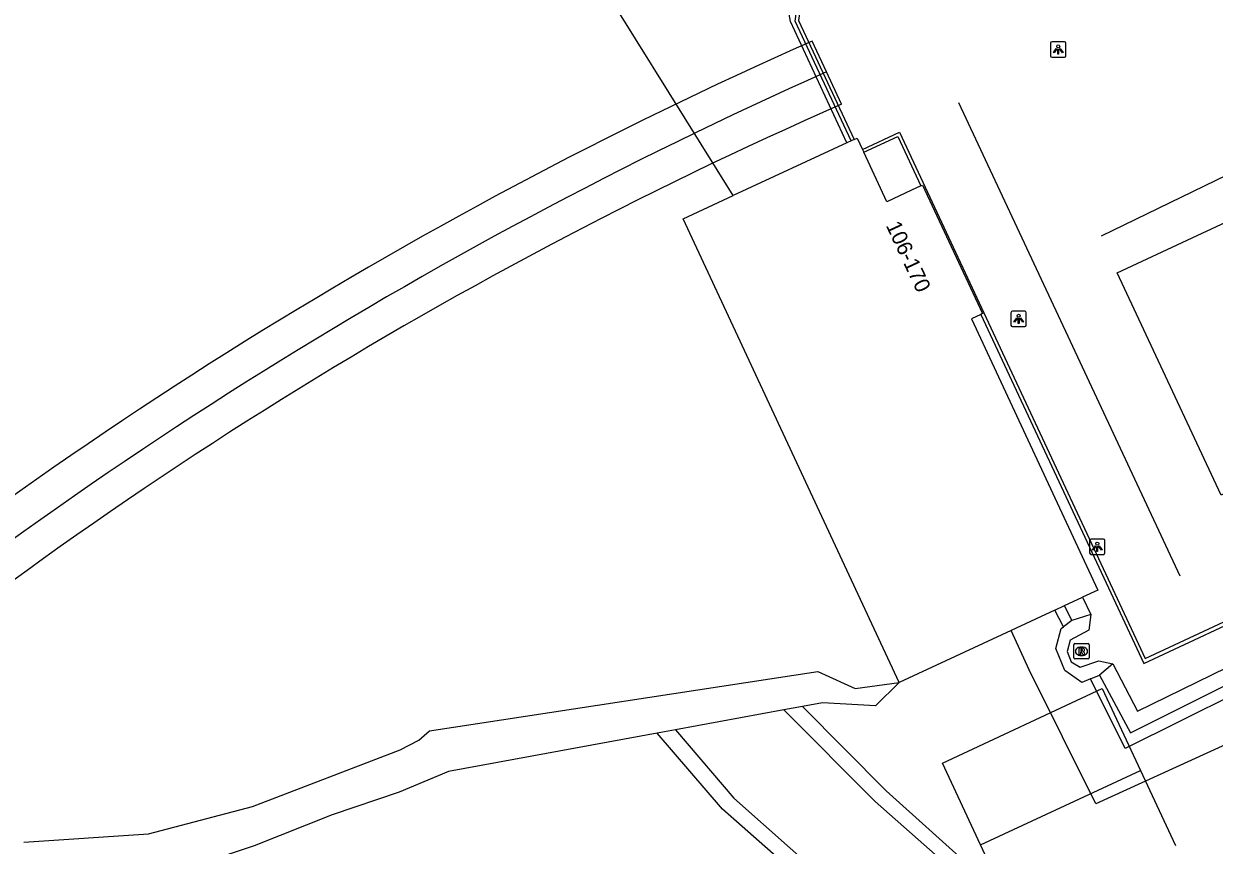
# Model space of a CAD drawing. Extents: x 155640 to 156810, y 382822 to 384046.
# Drawn here: x 156352.8 to 156430.2, y 383607 to 383660.4 of the extents above; entities that cross this region are included whole.
import ezdxf

# ---------------------------------------------------------------- set-up
doc = ezdxf.new("R2010")
doc.units = 0
for name, color, linetype in [('IMGEO_Dek', 7, 'Continuous'), ('IMGEO_Fietspad_gesloten', 7, 'Continuous'), ('IMGEO_Groenvoorziening', 7, 'Continuous'), ('IMGEO_Lichtpunt', 7, 'Continuous'), ('IMGEO_Lijnafwatering', 7, 'Continuous'), ('IMGEO_Meer_plas_ven_vijver', 7, 'Continuous'), ('IMGEO_Muur', 7, 'Continuous'), ('IMGEO_Pand', 7, 'Continuous'), ('IMGEO_Pand_nummerreeks', 7, 'Continuous'), ('IMGEO_Pand_vergunning_verleend', 7, 'Continuous'), ('IMGEO_Rioolput', 7, 'Continuous'), ('IMGEO_Voetgangersgebied_gesloten', 7, 'Continuous'), ('IMGEO_Voetpad_open', 7, 'Continuous')]:
    doc.layers.add(name, color=color, linetype=linetype)

msp = doc.modelspace()

# ---------------------------------------------------------------- linework, layer by layer
at = {"layer": 'IMGEO_Dek'}
msp.add_lwpolyline([(156405.984, 383655.206), (156404.997, 383657.316), (156404.061, 383659.318)], dxfattribs=at)
for centre, radius, start, end in [((156524.71, 383386.919), 297.922, 113.88918, 130.50491), ((156520.895, 383392.973), 286.305, 113.66314, 130.7058)]:
    msp.add_arc(centre, radius, start, end, dxfattribs=at)
at = {"layer": 'IMGEO_Fietspad_gesloten'}
msp.add_lwpolyline([(156404.997, 383657.316), (156404.061, 383659.318)], dxfattribs=at)
for centre, radius, start, end in [((156524.71, 383386.919), 297.922, 113.88918, 130.50491), ((156526.23, 383385.16), 297.937, 114.01083, 130.50472)]:
    msp.add_arc(centre, radius, start, end, dxfattribs=at)
at = {"layer": 'IMGEO_Groenvoorziening'}
for points in [[(156423.637, 383618.795), (156425.236, 383615.708), (156449.521, 383627.575), (156458.696, 383607.173), (156460.114, 383604.619), (156489.605, 383581.396), (156489.812, 383580.164), (156489.269, 383579.114), (156487.523, 383577.898), (156486.752, 383578.045), (156485.235, 383578.757), (156457.287, 383600.998), (156455.379, 383602.928), (156453.641, 383605.853), (156447.188, 383620.939), (156422.522, 383609.671), (156418.19, 383618.402), (156417.016, 383620.957)], [(156422.776, 383618.049), (156424.785, 383614.287), (156449.137, 383626.484), (156456.722, 383608.221), (156458.385, 383605.29), (156459.691, 383603.715), (156488.187, 383581.203), (156487.643, 383580.547), (156459.772, 383602.626), (156457.864, 383604.504), (156456.117, 383607.727), (156449.565, 383623.152), (156448.725, 383624.069), (156447.36, 383624.401), (156446.083, 383624.028), (156424.433, 383613.283), (156422.191, 383617.807)], [(156421.652, 383623.116), (156422.197, 383621.989)], [(156420.973, 383621.613), (156420.487, 383622.573)], [(156420.426, 383621.202), (156419.863, 383622.283)], [(156420.973, 383621.613), (156420.426, 383621.202)], [(156422.197, 383621.989), (156422.08, 383620.972), (156420.869, 383620.328), (156420.673, 383619.584), (156420.925, 383618.907), (156421.504, 383618.559), (156422.734, 383618.972), (156423.637, 383618.795)], [(156422.197, 383621.989), (156420.973, 383621.613)], [(156422.191, 383617.807), (156421.617, 383617.569), (156420.502, 383618.345), (156419.933, 383619.784), (156420.283, 383621.094), (156420.426, 383621.202)], [(156423.637, 383618.795), (156422.776, 383618.049)], [(156422.191, 383617.807), (156422.776, 383618.049)], [(156409.738, 383617.568), (156408.186, 383616.056), (156404.738, 383616.259), (156403.435, 383616.019)], [(156402.228, 383615.797), (156395.166, 383614.497)], [(156403.435, 383616.019), (156402.228, 383615.797)], [(156403.435, 383616.019), (156408.885, 383610.517), (156456.925, 383567.29), (156469.743, 383551.737), (156475.686, 383545.302), (156477.499, 383542.266), (156478.635, 383538.351), (156478.41, 383535.519), (156475.332, 383528.135), (156473.875, 383523.767), (156474.636, 383528.369), (156477.059, 383535.306), (156477.459, 383538.408), (156475.537, 383543.744), (156456.156, 383566.696), (156427.539, 383592.711), (156408.16, 383609.82), (156402.228, 383615.797)], [(156393.975, 383614.278), (156380.396, 383611.779), (156377.186, 383610.428), (156372.832, 383608.955), (156367.751, 383606.932), (156362.36, 383605.144), (156360.509, 383604.92), (156355.802, 383604.715), (156350.93, 383604.322), (156345.618, 383604.627), (156343.174, 383604.953), (156342.007, 383605.17), (156339.567, 383605.891), (156335.993, 383608.654), (156334.174, 383610.012)], [(156395.166, 383614.497), (156393.975, 383614.278)], [(156468.184, 383540.764), (156464.582, 383545.494), (156461.269, 383549.707), (156451.177, 383560.656), (156405.557, 383602.864), (156398.24, 383609.323), (156393.975, 383614.278)], [(156395.166, 383614.497), (156398.976, 383610.039), (156406.313, 383603.538), (156451.888, 383561.364), (156461.963, 383550.599), (156465.016, 383546.221), (156468.005, 383541.974)]]:
    msp.add_lwpolyline(points, dxfattribs=at)
at = {"layer": 'IMGEO_Lichtpunt'}
for p, q in [((156419.583, 383659.179), (156419.583, 383658.372)), ((156419.583, 383659.179), (156419.583, 383658.372)), ((156420.485, 383659.274), (156419.677, 383659.274)), ((156420.485, 383659.274), (156419.677, 383659.274)), ((156420.579, 383658.372), (156420.579, 383659.179)), ((156420.579, 383658.372), (156420.579, 383659.179)), ((156419.677, 383658.278), (156420.485, 383658.278)), ((156419.677, 383658.278), (156420.485, 383658.278)), ((156417.91, 383641.739), (156417.102, 383641.739)), ((156417.91, 383641.739), (156417.102, 383641.739)), ((156417.008, 383641.644), (156417.008, 383640.837)), ((156417.008, 383641.644), (156417.008, 383640.837)), ((156418.004, 383640.837), (156418.004, 383641.644)), ((156418.004, 383640.837), (156418.004, 383641.644)), ((156417.102, 383640.743), (156417.91, 383640.743)), ((156417.102, 383640.743), (156417.91, 383640.743)), ((156422.124, 383626.813), (156422.124, 383626.006)), ((156422.124, 383626.813), (156422.124, 383626.006)), ((156423.026, 383626.908), (156422.218, 383626.908)), ((156423.026, 383626.908), (156422.218, 383626.908)), ((156423.12, 383626.006), (156423.12, 383626.813)), ((156423.12, 383626.006), (156423.12, 383626.813)), ((156422.218, 383625.912), (156423.026, 383625.912)), ((156422.218, 383625.912), (156423.026, 383625.912))]:
    msp.add_line(p, q, dxfattribs=at)
for points in [[(156419.957, 383658.843), (156419.996, 383658.815), (156419.808, 383658.553), (156419.77, 383658.58), (156419.957, 383658.843)], [(156420.059, 383658.795), (156420.106, 383658.795), (156420.106, 383658.473), (156420.059, 383658.473), (156420.059, 383658.795)], [(156420.169, 383658.815), (156420.207, 383658.842), (156420.394, 383658.58), (156420.355, 383658.552), (156420.169, 383658.815)], [(156417.382, 383641.308), (156417.421, 383641.28), (156417.233, 383641.018), (156417.195, 383641.045), (156417.382, 383641.308)], [(156417.484, 383641.26), (156417.531, 383641.26), (156417.531, 383640.938), (156417.484, 383640.938), (156417.484, 383641.26)], [(156417.594, 383641.28), (156417.632, 383641.307), (156417.819, 383641.045), (156417.78, 383641.017), (156417.594, 383641.28)], [(156422.498, 383626.477), (156422.537, 383626.449), (156422.349, 383626.187), (156422.311, 383626.214), (156422.498, 383626.477)], [(156422.6, 383626.429), (156422.647, 383626.429), (156422.647, 383626.107), (156422.6, 383626.107), (156422.6, 383626.429)], [(156422.71, 383626.449), (156422.748, 383626.476), (156422.935, 383626.214), (156422.896, 383626.186), (156422.71, 383626.449)]]:
    msp.add_lwpolyline(points, dxfattribs=at)
for centre in [(156420.082, 383658.977), (156417.507, 383641.442), (156422.623, 383626.611)]:
    msp.add_circle(centre, 0.0994, dxfattribs=at)
for centre, start, end in [((156419.677, 383659.179), 90, 180), ((156419.677, 383659.179), 90, 180), ((156420.485, 383659.179), 0, 90), ((156420.485, 383659.179), 0, 90), ((156419.677, 383658.372), 180, 270), ((156419.677, 383658.372), 180, 270), ((156420.485, 383658.372), 270, 0), ((156420.485, 383658.372), 270, 360), ((156417.102, 383641.644), 90, 180), ((156417.102, 383641.644), 90, 180), ((156417.91, 383641.644), 0, 90), ((156417.91, 383641.644), 0, 90), ((156417.102, 383640.837), 180, 270), ((156417.102, 383640.837), 180, 270), ((156417.91, 383640.837), 270, 0), ((156417.91, 383640.837), 270, 360), ((156422.218, 383626.813), 90, 180), ((156422.218, 383626.813), 90, 180), ((156423.026, 383626.813), 0, 90), ((156423.026, 383626.813), 0, 90), ((156422.218, 383626.006), 180, 270), ((156422.218, 383626.006), 180, 270), ((156423.026, 383626.006), 270, 0), ((156423.026, 383626.006), 270, 360)]:
    msp.add_arc(centre, 0.0946, start, end, dxfattribs=at)
at = {"layer": 'IMGEO_Lijnafwatering'}
for points in [[(156413.59, 383655.325), (156420.698, 383640.125)], [(156422.906, 383646.649), (156440.016, 383654.951)], [(156420.698, 383640.125), (156427.998, 383624.514)]]:
    msp.add_lwpolyline(points, dxfattribs=at)
at = {"layer": 'IMGEO_Meer_plas_ven_vijver'}
for points in [[(156398.921, 383649.266), (156388.405, 383666.182)], [(156352.753, 383607.187), (156360.877, 383607.728), (156367.645, 383609.501), (156377.261, 383613.187), (156378.466, 383613.825), (156379.163, 383614.421), (156404.434, 383618.287), (156406.868, 383617.171), (156409.738, 383617.568)]]:
    msp.add_lwpolyline(points, dxfattribs=at)
at = {"layer": 'IMGEO_Muur'}
for points in [[(156409.602, 383685.242), (156407.185, 383679.634), (156406.522, 383675.039), (156405.194, 383675.202), (156403.183, 383660.665), (156406.798, 383652.916)], [(156406.607, 383652.828), (156402.962, 383660.62), (156405.007, 383675.431)], [(156407.34, 383652.267), (156409.758, 383653.398), (156425.737, 383619.126), (156450.602, 383630.716), (156462.175, 383605.969), (156467.181, 383608.237), (156467.858, 383606.862), (156505.409, 383577.593), (156505.213, 383577.392), (156487.476, 383541.686), (156478.262, 383529.882), (156478.847, 383529.078), (156488.235, 383516.182)], [(156407.426, 383652.083), (156409.651, 383653.114), (156411.15, 383649.901)], [(156415.055, 383641.53), (156425.658, 383618.803), (156450.441, 383630.387), (156462.081, 383605.554), (156467.059, 383607.851), (156467.609, 383606.673), (156504.975, 383577.57), (156487.254, 383541.827), (156477.937, 383529.89), (156478.682, 383528.865)]]:
    msp.add_lwpolyline(points, dxfattribs=at)
at = {"layer": 'IMGEO_Pand'}
for points in [[(156454.553, 383640.906), (156430.689, 383629.765), (156423.924, 383644.238), (156458.601, 383660.428)], [(156406.329, 383652.699), (156398.921, 383649.266)], [(156406.607, 383652.828), (156406.329, 383652.699)], [(156406.798, 383652.916), (156406.607, 383652.828)], [(156406.798, 383652.916), (156406.994, 383653.007), (156407.34, 383652.267)], [(156407.34, 383652.267), (156407.426, 383652.083)], [(156411.15, 383649.901), (156410.541, 383649.616), (156408.931, 383648.863), (156407.426, 383652.083)], [(156411.15, 383649.901), (156411.248, 383649.947), (156415.163, 383641.581), (156415.055, 383641.53)], [(156409.738, 383617.568), (156395.678, 383647.763), (156398.921, 383649.266)], [(156415.055, 383641.53), (156414.442, 383641.243), (156422.668, 383623.589), (156421.652, 383623.116)], [(156420.487, 383622.573), (156421.652, 383623.116)], [(156419.863, 383622.283), (156420.487, 383622.573)], [(156419.863, 383622.283), (156417.016, 383620.957)], [(156417.016, 383620.957), (156409.738, 383617.568)]]:
    msp.add_lwpolyline(points, dxfattribs=at)
at = {"layer": 'IMGEO_Pand_vergunning_verleend'}
for points in [[(156415.022, 383606.996), (156412.546, 383612.314), (156422.95, 383617.171), (156425.432, 383611.848)], [(156415.022, 383606.996), (156425.432, 383611.848)], [(156425.432, 383611.848), (156427.709, 383606.967)], [(156417.297, 383602.11), (156415.022, 383606.996)]]:
    msp.add_lwpolyline(points, dxfattribs=at)
at = {"layer": 'IMGEO_Rioolput'}
for p, q in [((156421.096, 383619.176), (156421.096, 383620.028)), ((156421.171, 383620.102), (156422.023, 383620.102)), ((156422.097, 383620.028), (156422.097, 383619.176)), ((156421.607, 383619.322), (156421.582, 383619.322)), ((156421.584, 383619.882), (156421.609, 383619.882)), ((156422.023, 383619.102), (156421.171, 383619.102))]:
    msp.add_line(p, q, dxfattribs=at)
for points in [[(156421.096, 383619.176), (156421.096, 383620.028)], [(156421.171, 383620.102), (156422.023, 383620.102)], [(156422.097, 383620.028), (156422.097, 383619.176)], [(156421.685, 383619.8), (156421.433, 383619.802), (156421.433, 383619.402)], [(156421.433, 383619.402), (156421.557, 383619.402), (156421.557, 383619.564), (156421.568, 383619.564)], [(156421.611, 383619.721), (156421.557, 383619.721), (156421.557, 383619.64)], [(156421.557, 383619.64), (156421.609, 383619.64)], [(156421.615, 383619.535), (156421.686, 383619.402), (156421.826, 383619.402), (156421.761, 383619.528)], [(156422.023, 383619.102), (156421.171, 383619.102)]]:
    msp.add_lwpolyline(points, dxfattribs=at)
for centre, radius, start, end in [((156421.173, 383620.026), 0.0765, 91.55205, 178.44795), ((156421.173, 383620.026), 0.0765, 91.55205, 178.44795), ((156422.021, 383620.026), 0.0765, 1.55205, 88.44795), ((156422.021, 383620.026), 0.0765, 1.55205, 88.44795), ((156421.567, 383619.511), 0.0533, 26.02933, 88.69889), ((156421.593, 383619.829), 0.19, 274.7715, 282.96867), ((156421.617, 383619.625), 0.0964, 77.00612, 93.18647), ((156421.631, 383619.682), 0.0378, 276.66336, 79.67722), ((156421.684, 383619.69), 0.109, 350.36119, 89.41601), ((156421.682, 383619.69), 0.112, 277.58423, 350.98172), ((156421.666, 383619.475), 0.108, 29.51342, 73.79051), ((156421.173, 383619.178), 0.0765, 181.55205, 268.44795), ((156421.173, 383619.178), 0.0765, 181.55205, 268.44795), ((156422.021, 383619.178), 0.0765, 271.55205, 358.44795), ((156422.021, 383619.178), 0.0765, 271.55205, 358.44795)]:
    msp.add_arc(centre, radius, start, end, dxfattribs=at)
for centre, major_axis, ratio, start_param, end_param in [((156421.583, 383619.602), (-0.387, 0.002), 0.722429, 4.712389, 7.853982), ((156421.608, 383619.602), (-0.39, 0.002), 0.717154, 1.570796, 4.712389)]:
    msp.add_ellipse(centre, major_axis=major_axis, ratio=ratio, start_param=start_param, end_param=end_param, dxfattribs=at)
at = {"layer": 'IMGEO_Voetgangersgebied_gesloten'}
msp.add_lwpolyline([(156405.984, 383655.206), (156404.997, 383657.316)], dxfattribs=at)
msp.add_arc((156520.895, 383392.973), 286.305, 113.66314, 130.7058, dxfattribs=at)
at = {"layer": 'IMGEO_Voetpad_open'}
msp.add_lwpolyline([(156406.329, 383652.699), (156402.667, 383660.593), (156400.777, 383671.143)], dxfattribs=at)

# ---------------------------------------------------------------- texts
at = {"layer": 'IMGEO_Pand_nummerreeks'}
msp.add_text('106-170', height=1, rotation=294.98075, dxfattribs=at).set_placement((156408.852, 383647.319))

doc.saveas('drawing.dxf')
